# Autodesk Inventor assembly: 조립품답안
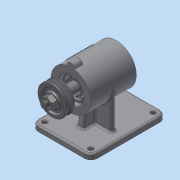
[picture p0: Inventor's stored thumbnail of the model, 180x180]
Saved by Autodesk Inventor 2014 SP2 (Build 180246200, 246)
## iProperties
Created: 2015-12
Part Number: 조립품답안
Document SubType Name: Assembly
Designer: 201-19
Author: 201-19
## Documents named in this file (7)
- C:\Users\201-19\Desktop\451207V1023\조립품답안.iam
- C:\Users\201-19\Desktop\451207V1023\본체.ipt
- C:\Users\201-19\Desktop\451207V1023\베어링 6204.ipt
- C:\Users\201-19\Desktop\451207V1023\축.ipt
- C:\Users\201-19\Desktop\451207V1023\키(4 x 4 x 12).ipt
- C:\Users\201-19\Desktop\451207V1023\V-벨트풀리.ipt
- C:\Users\201-19\Desktop\451207V1023\너트 M12x1.25.ipt
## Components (5 placed, 4 different names)
1. KS B 2023 6204 - 20 x 47 x 14:1
2. KS B 2023 6204 - 20 x 47 x 14:2
3. KS B 1311 (I) 4 x 4 x 12:1 — 각도:1
4. V-벨트풀리:1
5. KS B 1012 클래스 1 일반 - 미터 M12x1.25:1
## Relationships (1: Angle 1)
- 각도:1 [Angle]: KS B 1311 (I) 4 x 4 x 12:1
